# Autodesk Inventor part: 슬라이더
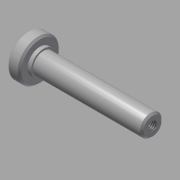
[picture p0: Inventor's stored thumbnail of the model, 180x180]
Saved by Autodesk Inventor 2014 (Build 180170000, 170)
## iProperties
Created: 2011-04
Part Number: 슬라이더
Document SubType Name: Modeling
Designer: 한국산업디자인학원 [http://gmhk.co.kr]
Density: 7.86 g/cm^3
Material: 강철, 연강
Appearance: 강철
Mass: 76.7999 g
Surface Area: 38.1769 cm^2
Volume: 9.77098 cm^3
Author: pww
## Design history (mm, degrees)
sketch "스케치1"
  geometry: L1 (-7, 0)-(63, 0); L2 (63, 0)-(63, 6); L3 (63, 6)-(0, 6); L4 (-7, 0)-(-7, 11.5); L5 (-7, 11.5)-(0, 11.5); L6 (0, 11.5)-(0, 6); 1 further point
  constraints: 12 end point, 3 perpendicular, 2 horizontal, 2 point on line, 1 parallel
  dimensions: "d1" = 70 distance of L1.start L1.end; "d19" = 12 diameter of L3 L1; "d20" = 7 distance of L4.end L5.end; "d21" = 23 diameter of L5 L1
revolve "회전1" stored, may be unused: angle "d4" = 90 deg
chamfer "모따기1" distance "d16" = 1; stored, may be unused: second distance "d17" = 2, angle "d18" = 45 deg
hole "구멍2" diameter "d24" = 4.917; stored, may be unused: countersink angle "d28" = 90 deg, drill point angle "d30" = 118 deg; dims "d22" = 10, "d23" = 10, "d25" = 10, "d26" = 4, "d27" = 2, "d29" = 13
sketch "스케치2"
  geometry: C1 r 7 at (0, 0); 1 further point
  constraints: 1 centre point, 1 coincident
  dimensions: "d31" = 14 diameter of C1
extrude "돌출2" join sketch "스케치2" distance "d32" = 2; taper "d33" = 0 deg
node "솔리드1"
